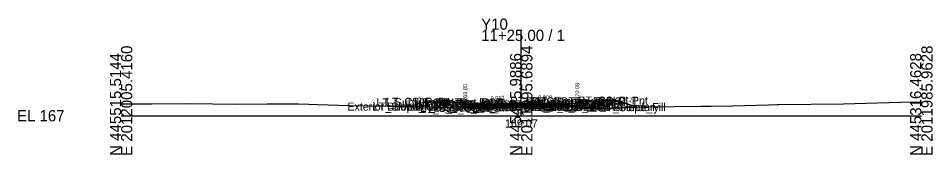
# Model space of a CAD drawing. Extents: x -26 to 203, y -10 to 3517.
# Drawn here: x -25.7 to 202.8, y 2490.3 to 2524.3 of the extents above; entities that cross this region are included whole.
import ezdxf

# ---------------------------------------------------------------- set-up
doc = ezdxf.new("R2010")
doc.units = 0
for name, color, linetype in [('Default', 7, 'Continuous'), ('Exist Cross Section Cell', 7, 'Continuous'), ('Exist XS Center Line Elevation Label', 7, 'Continuous'), ('Exist XS Ground Line', 7, 'Continuous'), ('Prop CMT Conc Surface', 7, 'Continuous'), ('Prop CMT Concrete Structures', 7, 'Continuous'), ('Prop CMT Pvmt Course 1', 7, 'Continuous'), ('Prop CMT Pvmt Course 1 CG', 7, 'Continuous'), ('Prop CMT Pvmt Course 2', 7, 'Continuous'), ('Prop CMT Pvmt Course 3', 7, 'Continuous'), ('Prop CMT Pvmt Surface', 7, 'Continuous'), ('Prop CMT Slope Grass', 7, 'Continuous'), ('Prop CMT Subgrade Earthwork', 7, 'Continuous'), ('Prop XS Earthwork Shape', 7, 'Continuous'), ('Prop XS Hydro Elevations', 7, 'Continuous'), ('Prop XS SE Text', 7, 'Continuous'), ('Prop XS Side Slope Text', 7, 'Continuous'), ('Scratch_Level_0', 7, 'Continuous')]:
    doc.layers.add(name, color=color, linetype=linetype)

msp = doc.modelspace()

# ---------------------------------------------------------------- linework, layer by layer
at = {"layer": 'Exist Cross Section Cell'}
for p, q in [((100, 2500), (100, 2521.42)), ((0, 2500), (100, 2500)), ((100, 2500), (200, 2500))]:
    msp.add_line(p, q, dxfattribs=at)
at = {"layer": 'Exist XS Ground Line'}
msp.add_lwpolyline([(0, 2503), (0.56, 2503), (7.69, 2502.98), (17.24, 2503.04), (28.52, 2502.92), (36.54, 2502.99), (44.32, 2502.94), (46.93, 2502.91), (49.07, 2502.83), (56.98, 2502.51), (66.59, 2502.38), (67.03, 2502.37), (71.02, 2502.31), (76.54, 2502.22), (77.35, 2502.21), (87.78, 2501.85), (88.14, 2501.82), (88.46, 2501.69), (96.56, 2502), (99.26, 2502.13), (100, 2502.07), (102.09, 2501.9), (112.01, 2501.29), (112.47, 2501.34), (112.82, 2501.71), (113.38, 2501.76), (118.67, 2501.9), (119.09, 2501.92), (123.5, 2502), (130.64, 2502.19), (131.39, 2502.2), (145.01, 2502.41), (147.49, 2502.41), (152.82, 2502.49), (155.81, 2502.58), (161.8, 2502.74), (163.88, 2502.76), (164.27, 2502.76), (180.55, 2502.94), (197.66, 2503.43), (200, 2503.36)], dxfattribs=at)
at = {"layer": 'Prop CMT Conc Surface'}
for points in [[(86, 2502.8), (86, 2503.3), (85.5, 2503.3)], [(88, 2502.9), (86, 2502.8)], [(112, 2503.14), (114, 2503.08)], [(114, 2503.08), (114, 2503.58), (114.5, 2503.58)]]:
    msp.add_lwpolyline(points, dxfattribs=at)
at = {"layer": 'Prop CMT Concrete Structures'}
for points in [[(88, 2502.9), (86, 2502.8), (86, 2503.3), (85.5, 2503.3)], [(85.5, 2503.3), (85.5, 2502.29), (88, 2502.32)], [(88, 2502.32), (88, 2502.9)], [(112, 2503.14), (114, 2503.08), (114, 2503.58), (114.5, 2503.58)], [(114.5, 2503.58), (114.5, 2502.58), (112, 2502.56)], [(112, 2502.56), (112, 2503.14)]]:
    msp.add_lwpolyline(points, dxfattribs=at)
at = {"layer": 'Prop CMT Pvmt Course 1'}
for points in [[(100, 2503.05), (88, 2502.9)], [(88, 2502.9), (88, 2502.65)], [(88, 2502.65), (100, 2502.8)], [(100, 2503.05), (112, 2503.14)], [(100, 2502.8), (100, 2503.05)], [(100, 2502.8), (100, 2503.05)], [(112, 2502.89), (100, 2502.8)], [(112, 2503.14), (112, 2502.89)]]:
    msp.add_lwpolyline(points, dxfattribs=at)
msp.add_lwpolyline([(100, 2502.8), (100, 2502.93), (100, 2502.93), (100, 2502.8)], close=True, dxfattribs=at)
msp.add_lwpolyline([(100, 2502.8), (100, 2502.93), (100, 2502.93), (100, 2502.8)], close=True, dxfattribs=at)
at = {"layer": 'Prop CMT Pvmt Course 1 CG'}
for points in [[(112, 2502.56), (115, 2502.58), (115.33, 2502.25)], [(112, 2502.23), (112, 2502.56)], [(88, 2502.32), (85, 2502.28), (84.66, 2501.95)], [(84.66, 2501.95), (88, 2501.99)], [(88, 2501.99), (88, 2502.32)], [(115.33, 2502.25), (112, 2502.23)]]:
    msp.add_lwpolyline(points, dxfattribs=at)
at = {"layer": 'Prop CMT Pvmt Course 2'}
for points in [[(100, 2502.8), (88, 2502.65)], [(88, 2502.65), (88, 2502.32)], [(88, 2502.32), (100, 2502.47)], [(100, 2502.8), (112, 2502.89)], [(100, 2502.47), (100, 2502.8)], [(100, 2502.47), (100, 2502.8)], [(112, 2502.56), (100, 2502.47)], [(112, 2502.89), (112, 2502.56)]]:
    msp.add_lwpolyline(points, dxfattribs=at)
at = {"layer": 'Prop CMT Pvmt Course 3'}
for points in [[(100, 2502.47), (88, 2502.32)], [(100, 2502.47), (112, 2502.56)], [(100, 2502.14), (100, 2502.47)], [(100, 2502.14), (100, 2502.47)], [(112, 2502.56), (112, 2502.23)], [(88, 2502.32), (88, 2501.99)], [(88, 2501.99), (100, 2502.14)], [(112, 2502.23), (100, 2502.14)]]:
    msp.add_lwpolyline(points, dxfattribs=at)
at = {"layer": 'Prop CMT Pvmt Surface'}
for points in [[(100, 2503.05), (88, 2502.9)], [(100, 2503.05), (112, 2503.14)]]:
    msp.add_lwpolyline(points, dxfattribs=at)
at = {"layer": 'Prop CMT Slope Grass'}
for points in [[(85.5, 2503.3), (76, 2503.49), (72.4, 2502.29)], [(114.5, 2503.58), (124, 2503.77), (128.87, 2502.15)]]:
    msp.add_lwpolyline(points, dxfattribs=at)
at = {"layer": 'Prop CMT Subgrade Earthwork'}
for points in [[(88, 2501.99), (84.66, 2501.95), (83.26, 2503.34)], [(112, 2502.23), (115.33, 2502.25), (116.7, 2503.62)], [(100, 2502.14), (88, 2501.99)], [(100, 2502.14), (112, 2502.23)]]:
    msp.add_lwpolyline(points, dxfattribs=at)
at = {"layer": 'Prop XS Earthwork Shape'}
for points in [[(76, 2503.49), (72.4, 2502.29), (76.54, 2502.22), (77.35, 2502.21), (84.65, 2501.96), (83.26, 2503.34)], [(100, 2502.07), (102.09, 2501.9), (112.01, 2501.29), (112.47, 2501.34), (112.82, 2501.71), (113.38, 2501.76), (118.67, 2501.9), (119.09, 2501.92), (123.5, 2502), (128.87, 2502.15), (124, 2503.77), (116.7, 2503.62), (115.33, 2502.25), (112, 2502.23), (100, 2502.14), (99.28, 2502.13)], [(84.66, 2501.95), (84.65, 2501.96), (84.92, 2501.95)], [(84.92, 2501.95), (87.78, 2501.85), (88.14, 2501.82), (88.46, 2501.69), (96.56, 2502), (99.2, 2502.13), (88, 2501.99)]]:
    msp.add_lwpolyline(points, close=True, dxfattribs=at)

# ---------------------------------------------------------------- texts
at = {"layer": 'Default'}
msp.add_text('-', height=0.0001, dxfattribs=at).set_placement((0, 2500))
at = {"layer": 'Exist Cross Section Cell'}
for s, p in [('Y10', (90, 2521.42)), ('11+25.00 / 1', (90, 2518.62)), ('EL 167', (-26, 2498.6))]:
    msp.add_text(s, height=2.8, dxfattribs=at).set_placement(p)
for s, p in [('E 2012005.4160', (2.8, 2490)), ('E 2011995.6894', (102.8, 2490)), ('E 2011985.9628', (202.8, 2490)), ('N 445515.5144', (0, 2490)), ('N 445415.9886', (100, 2490)), ('N 445316.4628', (200, 2490))]:
    msp.add_text(s, height=2.8, rotation=90, dxfattribs=at).set_placement(p)
at = {"layer": 'Exist XS Center Line Elevation Label'}
msp.add_text('169.07', height=2, dxfattribs=at).set_placement((95.94, 2497.07))
at = {"layer": 'Prop XS Hydro Elevations'}
for s, p in [('169.80', (86.5, 2503.69)), ('170.08', (114.5, 2503.97))]:
    msp.add_text(s, height=1, rotation=90, dxfattribs=at).set_placement(p)
at = {"layer": 'Prop XS SE Text'}
msp.add_text('0.013', height=1, rotation=1.1458, dxfattribs=at).set_placement((92.37, 2503.9))
msp.add_text('0.008', height=1, dxfattribs=at).set_placement((104.25, 2504.05))
at = {"layer": 'Prop XS Side Slope Text'}
for rotation, p in [(18.4332, (73.36, 2503.29)), (341.5668, (125.77, 2503.86))]:
    msp.add_text('3:1', height=1, rotation=rotation, dxfattribs=at).set_placement(p)
at = {"layer": 'Scratch_Level_0'}
for s, p in [('RT_Sub_Trench_Out_DLT', (97.22, 2502.62)), ('RT_CSLP_Pnt', (114.13, 2502.77)), ('Exterior Boundary', (56.54, 2501.29)), ('LT_Slope_Fill', (62.92, 2501.29)), ('LT_Sub_Trench_Out_DLT', (63.83, 2502.34)), ('LT_CSLP_Pnt', (66.17, 2502.49)), ('LT_CG1_Shelf_Out', (71.55, 2501.28)), ('LT_CG_Top_Face', (73.26, 2502.3)), ('LT_CG_Top_BOC', (73.78, 2502.3)), ('LT_CG_Bot_BOC', (73.81, 2501.29)), ('LT_CG_Top_Gut', (74.24, 2501.8)), ('LT_Sub_OEOP', (74.77, 2500.95)), ('LT_CG_Bot_IE', (77.91, 2501.32)), ('LT_Sub_OEOT', (78.08, 2500.99)), ('LT_PV2_OEOT', (78.17, 2501.65)), ('LT_PV3_OEOT', (78.17, 2501.32)), ('LT_PV1_OEOT', (78.74, 2501.9)), ('RT_Sub_OEEOP', (89.17, 2501.14)), ('LT_Sub_OEEOP', (89.21, 2501.14)), ('RT_PV2_OEEOP', (89.26, 2501.8)), ('RT_PV3_OEEOP', (89.26, 2501.47)), ('LT_PV2_OEEOP', (89.31, 2501.8)), ('LT_PV3_OEEOP', (89.31, 2501.47)), ('RT_PV1_OEEOP', (89.83, 2501.93)), ('LT_PV1_OEEOP', (89.87, 2501.93)), ('RT_PV2_IEEOP', (89.91, 2501.8)), ('LT_PV2_IEEOP', (89.95, 2501.8)), ('RT_PV1_IEEOP', (90.47, 2501.93)), ('LT_PV1_IEEOP', (90.52, 2501.93)), ('PV2_PGL', (93.91, 2501.8)), ('PV1_PGL', (94.47, 2502.05)), ('RT_CG_Top_Face', (101.21, 2502.58)), ('RT_CG1_Shelf_Out', (101.5, 2501.58)), ('RT_CG_Bot_IE', (101.87, 2501.56)), ('RT_Sub_OEOT', (102.03, 2501.23)), ('RT_PV2_OEOT', (102.13, 2501.89)), ('RT_PV3_OEOT', (102.13, 2501.56)), ('RT_CG_Top_Gut', (102.19, 2502.08)), ('RT_PV1_OEOT', (102.69, 2502.14)), ('RT_CG_Top_BOC', (102.74, 2502.58)), ('RT_CG_Bot_BOC', (102.77, 2501.58)), ('RT_Sub_OEOP', (105.39, 2501.25)), ('Exterior Boundary', (113.01, 2501.15)), ('RT_Slope_Fill', (119.34, 2501.15))]:
    msp.add_text(s, height=2, dxfattribs=at).set_placement(p)

doc.saveas('drawing.dxf')
